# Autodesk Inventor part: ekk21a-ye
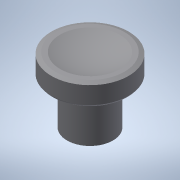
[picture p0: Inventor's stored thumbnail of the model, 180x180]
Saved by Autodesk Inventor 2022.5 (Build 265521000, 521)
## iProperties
Created: 2016-12
Part Number: ekk21a-ye
Material: 一般
Document SubType Name: Modeling
Designer: imaocorp
Density: 1 g/cm^3
Appearance: 既定
Author: imaocorp
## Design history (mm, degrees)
node "ekk21a-ye.x_t1"
node "ekk21a-ye"
node "Base1"
